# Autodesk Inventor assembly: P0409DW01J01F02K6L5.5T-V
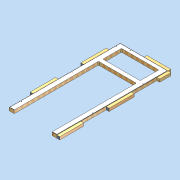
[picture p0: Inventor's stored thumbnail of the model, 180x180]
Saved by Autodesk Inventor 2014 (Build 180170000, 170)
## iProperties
Created: 2011-04
Part Number: P0409DW01J01F02K6L5.5T-V
Document SubType Name: Assembly
Designer: david.appleford
Description: 1w x 2.25w 01 Door/Window Panel - 6 Locks 5.5 Lugs
Mass: 15000 g
Surface Area: 37194.2 cm^2
Volume: 79418.5 cm^3
Density: 0.188873 g/cm^3
Cost Center: £179.00
Justset: False
Title: 1w x 2.25w 01 Panel - 6 Locks 5.5 Lugs
Author: david.appleford
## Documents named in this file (5)
- C:\Documents and Settings\john.everitt\Local Settings\My Documents\Vault\Production MkII\Virtual Elements\Virtual Walls\Virtual Timber + MgO\P0409DW01J01F02K6L5.5T-V.iam
- C:\Documents and Settings\john.everitt\Local Settings\My Documents\Vault\Production MkII\VIRTUAL ELEMENTS\Virtual Lugs\Superceded Lugs\LA02C3V.ipt
- C:\Documents and Settings\john.everitt\Local Settings\My Documents\Vault\Production MkII\VIRTUAL ELEMENTS\Virtual Lugs\Superceded Lugs\LA02M3V.ipt
- C:\Documents and Settings\john.everitt\Local Settings\My Documents\Vault\Production MkII\VIRTUAL ELEMENTS\Virtual Lugs\Superceded Lugs\LA01C3V.ipt
- C:\Documents and Settings\john.everitt\Local Settings\My Documents\Vault\Production MkII\Virtual Elements\Virtual Walls\Virtual Timber + MgO\P0409DW01J01F02K7-V.ipt
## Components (7 placed, 4 different names)
1. P0409DW01J01F02K7-V:1 — Mate:1, Flush:1, Flush:2, Mate:4, Flush:7, Flush:8, Mate:5, Mate:6, Flush:9, Flush:10, Mate:7, Flush:11, Mate:14, Flush:12, Flush:13
2. LA02C3V:1 — Mate:1, Flush:1, Flush:2, Mate:9, Mate:13
3. LA02C3V:3 — Mate:4, Flush:7, Flush:8
4. LA02M3V:5 — Mate:6, Flush:9, Mate:12
5. LA02M3V:2 — Mate:5, Flush:10, Mate:12, Mate:13
6. LA02M3V:4 — Mate:7, Flush:11, Mate:9
7. LA01C3V:1 — Mate:14, Flush:12, Flush:13
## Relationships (18: Mate 9, Flush 9)
- Mate:1: P0409DW01J01F02K7-V:1 ↔ LA02C3V:1
- Flush:1: P0409DW01J01F02K7-V:1 ↔ LA02C3V:1
- Flush:2: P0409DW01J01F02K7-V:1 ↔ LA02C3V:1
- Mate:4: P0409DW01J01F02K7-V:1 ↔ LA02C3V:3
- Flush:7: P0409DW01J01F02K7-V:1 ↔ LA02C3V:3
- Flush:8: P0409DW01J01F02K7-V:1 ↔ LA02C3V:3
- Mate:5: P0409DW01J01F02K7-V:1 ↔ LA02M3V:2
- Mate:6: P0409DW01J01F02K7-V:1 ↔ LA02M3V:5
- Flush:9: P0409DW01J01F02K7-V:1 ↔ LA02M3V:5
- Flush:10: P0409DW01J01F02K7-V:1 ↔ LA02M3V:2
- Mate:7: P0409DW01J01F02K7-V:1 ↔ LA02M3V:4
- Flush:11: P0409DW01J01F02K7-V:1 ↔ LA02M3V:4
- Mate:9: LA02C3V:1 ↔ LA02M3V:4
- Mate:12: LA02M3V:5 ↔ LA02M3V:2
- Mate:13: LA02C3V:1 ↔ LA02M3V:2
- Mate:14: P0409DW01J01F02K7-V:1 ↔ LA01C3V:1
- Flush:12: P0409DW01J01F02K7-V:1 ↔ LA01C3V:1
- Flush:13: P0409DW01J01F02K7-V:1 ↔ LA01C3V:1
## Named parameters: t = 1 mm, Cl = 2 mm
